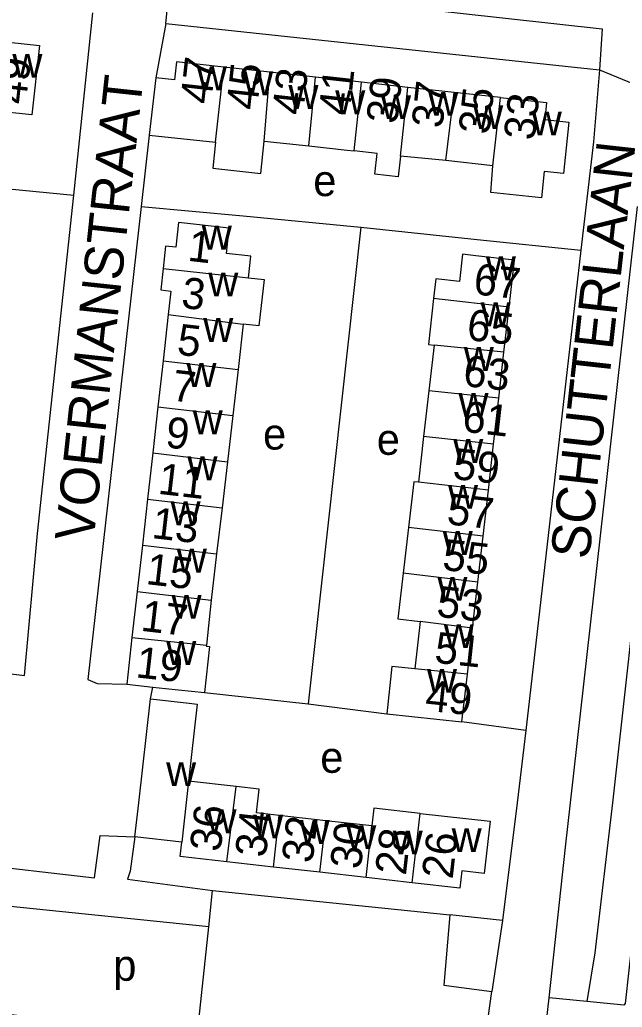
# Model space of a CAD drawing. Extents: x 161936 to 163647, y 386450 to 388633.
# Drawn here: x 162637.9 to 162715.4, y 387223.7 to 387350.8 of the extents above; entities that cross this region are included whole.
import ezdxf

# ---------------------------------------------------------------- set-up
doc = ezdxf.new("R2010")
doc.units = 0
for name, color, linetype in [('BLT_Basislijn', 7, 'Continuous'), ('BLT_Bebouwing', 7, 'Continuous'), ('BLT_Centroide', 7, 'Continuous'), ('BLT_Huisnummer', 7, 'Continuous'), ('BLT_Huisnummer_ tussenligend', 7, 'Continuous'), ('BLT_Onderverdeling_panden', 7, 'Continuous'), ('BLT_Straatnaam', 7, 'Continuous'), ('BLT_Vlakafsluiter', 7, 'Continuous')]:
    doc.layers.add(name, color=color, linetype=linetype)

msp = doc.modelspace()

# ---------------------------------------------------------------- linework, layer by layer
at = {"layer": 'BLT_Basislijn'}
for p, q in [((162656.65, 387350.3), (162657.23, 387355.77)), ((162644.82, 387328.18), (162647.28, 387351.66)), ((162656.65, 387350.3), (162655.35, 387343.29)), ((162656.65, 387350.3), (162712.42, 387344.32)), ((162724.15, 387340.98), (162714.12, 387250)), ((162654.53, 387335.94), (162653.5, 387326.75)), ((162708.71, 387250), (162717.32, 387326.72)), ((162681.73, 387324.06), (162674.96, 387262.75)), ((162710.03, 387321.12), (162702.97, 387259.3)), ((162654.7, 387263.39), (162654.97, 387264.9)), ((162661.63, 387264.19), (162674.96, 387262.75)), ((162674.96, 387262.75), (162685.1, 387261.47)), ((162702.97, 387259.3), (162694.74, 387260.41)), ((162702.97, 387259.3), (162701.83, 387250)), ((162701.83, 387250), (162699.98, 387234.84)), ((162708.08, 387244.31), (162708.71, 387250)), ((162705.96, 387224.92), (162708.08, 387244.31)), ((162662.18, 387234.04), (162662.64, 387238.71)), ((162662.64, 387238.71), (162693.18, 387235.57)), ((162699.98, 387234.84), (162693.18, 387235.57)), ((162660.69, 387219.97), (162662.18, 387234.04)), ((162699.98, 387234.84), (162698.57, 387225.71)), ((162697.71, 387219.57), (162698.57, 387225.71)), ((162705.32, 387219.12), (162705.96, 387224.92)), ((162710.8, 387224.44), (162705.96, 387224.92))]:
    msp.add_line(p, q, dxfattribs=at)
for points in [[(162657.23, 387355.77), (162712.78, 387349.62)], [(162712.78, 387349.62), (162712.42, 387344.32)], [(162712.42, 387344.32), (162711.67, 387335.06), (162710.03, 387321.12)], [(162616.29, 387331.01), (162631.13, 387329.54), (162644.82, 387328.18)], [(162629.16, 387267.52), (162631.11, 387267.3), (162638.46, 387266.37), (162640.15, 387284.64), (162644.82, 387328.18)], [(162653.5, 387326.75), (162646.61, 387265.85), (162647.84, 387265.35), (162651.62, 387265.26)], [(162653.5, 387326.75), (162666.58, 387325.52), (162681.73, 387324.06)], [(162681.73, 387324.06), (162696.69, 387322.5), (162710.03, 387321.12)], [(162714.12, 387250), (162711.86, 387230.69), (162710.8, 387224.44)], [(162623.39, 387248.74), (162629.53, 387248.09), (162629, 387242.28), (162631.09, 387242.25), (162647.49, 387240.34), (162648.2, 387245.8), (162652.68, 387245.62)], [(162652.68, 387245.62), (162652.07, 387241.22), (162651.72, 387240.16), (162662.64, 387238.71)], [(162662.18, 387234.04), (162636.24, 387236.71), (162634.86, 387222.99), (162660.69, 387219.97)], [(162693.18, 387235.57), (162692.4, 387226.54), (162698.57, 387225.71)], [(162716.7, 387232.75), (162715.73, 387224.18), (162715.57, 387223.96), (162710.8, 387224.44)]]:
    msp.add_lwpolyline(points, dxfattribs=at)
at = {"layer": 'BLT_Bebouwing'}
for p, q in [((162670.02, 387344.03), (162664.11, 387344.68)), ((162655.35, 387343.29), (162654.53, 387335.94)), ((162675.89, 387343.39), (162670.02, 387344.03)), ((162681.84, 387342.73), (162675.89, 387343.39)), ((162687.79, 387342.07), (162681.84, 387342.73)), ((162693.74, 387341.42), (162687.79, 387342.07)), ((162699.7, 387340.76), (162693.74, 387341.42)), ((162654.53, 387335.94), (162663.04, 387335)), ((162692.68, 387332.64), (162686.84, 387333.23)), ((162656.95, 387312.84), (162656.29, 387306.9)), ((162700.15, 387308.01), (162700.81, 387313.78)), ((162699.48, 387302.08), (162700.15, 387308.01)), ((162656.29, 387306.9), (162655.62, 387300.96)), ((162665.97, 387305.78), (162665.29, 387299.84)), ((162690.5, 387303.03), (162689.82, 387297.14)), ((162698.81, 387296.16), (162699.48, 387302.08)), ((162655.62, 387300.96), (162654.96, 387295.02)), ((162689.82, 387297.14), (162689.15, 387291.25)), ((162698.14, 387290.24), (162698.81, 387296.16)), ((162654.96, 387295.02), (162654.29, 387289.08)), ((162664.58, 387293.9), (162663.88, 387287.97)), ((162697.46, 387284.32), (162698.14, 387290.24)), ((162654.29, 387289.08), (162653.63, 387283.14)), ((162663.88, 387287.97), (162663.18, 387282.03)), ((162687.86, 387285.43), (162687.18, 387279.55)), ((162696.79, 387278.39), (162697.46, 387284.32)), ((162653.63, 387283.14), (162652.96, 387277.2)), ((162663.18, 387282.03), (162662.48, 387276.09)), ((162696.12, 387272.47), (162696.79, 387278.39)), ((162652.96, 387277.2), (162652.3, 387271.26)), ((162662.48, 387276.09), (162661.87, 387270.29)), ((162689.39, 387273.35), (162688.69, 387267.25)), ((162695.44, 387266.55), (162696.12, 387272.47)), ((162652.3, 387271.26), (162651.62, 387265.26)), ((162694.74, 387260.41), (162695.44, 387266.55)), ((162651.62, 387265.26), (162654.97, 387264.9)), ((162653.18, 387250), (162654.7, 387263.39)), ((162685.1, 387261.47), (162694.74, 387260.41)), ((162665.71, 387252.08), (162659.59, 387252.78)), ((162652.68, 387245.62), (162653.18, 387250)), ((162677.24, 387247.7), (162671.24, 387248.38)), ((162683.17, 387247.03), (162677.24, 387247.7)), ((162658.71, 387244.93), (162652.68, 387245.62)), ((162670.49, 387241.74), (162664.49, 387242.42)), ((162676.48, 387241.06), (162670.49, 387241.74)), ((162682.42, 387240.38), (162676.48, 387241.06)), ((162688.36, 387239.71), (162682.42, 387240.38))]:
    msp.add_line(p, q, dxfattribs=at)
for points in [[(162634.44, 387348.1), (162640.38, 387347.44), (162639.4, 387338.52), (162634.43, 387339.06), (162633.43, 387339.17)], [(162664.11, 387344.68), (162658.03, 387345.36), (162657.78, 387343.03), (162655.35, 387343.29)], [(162699.7, 387340.76), (162705.64, 387340.11), (162705.4, 387337.94), (162708.5, 387337.6), (162707.79, 387330.97), (162705.34, 387331.24), (162704.96, 387327.85), (162698.48, 387328.56), (162698.73, 387331.97)], [(162663.04, 387335), (162662.68, 387331.68), (162668.86, 387331), (162669.32, 387335.16)], [(162669.32, 387335.16), (162675.03, 387334.53)], [(162675.03, 387334.53), (162679.97, 387333.99), (162680.86, 387333.89)], [(162686.84, 387333.23), (162686.55, 387330.57), (162683.55, 387330.91), (162683.84, 387333.56), (162680.86, 387333.89)], [(162698.73, 387331.97), (162692.68, 387332.64)], [(162667.28, 387317.58), (162667.59, 387320.35), (162664.45, 387320.69), (162664.82, 387323.97), (162658.28, 387324.69), (162657.92, 387321.49), (162656.62, 387321.64), (162656.29, 387318.75)], [(162700.81, 387313.78), (162701.5, 387319.84), (162696.53, 387320.41), (162694.82, 387320.6), (162694.42, 387317.09), (162691.37, 387317.43), (162691.09, 387314.89)], [(162656.29, 387318.75), (162655.99, 387316), (162657.29, 387315.86), (162656.95, 387312.84)], [(162667.28, 387317.58), (162669.3, 387317.36), (162668.62, 387311.37), (162666.62, 387311.6)], [(162691.09, 387314.89), (162690.44, 387308.99), (162691.18, 387308.91)], [(162666.62, 387311.6), (162665.97, 387305.78)], [(162691.18, 387308.91), (162690.5, 387303.03)], [(162665.29, 387299.84), (162664.58, 387293.9)], [(162689.15, 387291.25), (162688.54, 387291.32), (162687.86, 387285.43)], [(162687.18, 387279.55), (162686.51, 387273.66), (162689.39, 387273.35)], [(162661.87, 387270.29), (162661.86, 387270.15), (162662.26, 387270.11), (162661.63, 387264.19)], [(162688.69, 387267.25), (162685.74, 387267.56), (162685.1, 387261.47)], [(162654.97, 387264.9), (162656.6, 387264.73), (162661.63, 387264.19)], [(162654.7, 387263.39), (162659.67, 387262.83), (162660.68, 387262.71), (162659.59, 387252.78)], [(162671.24, 387248.38), (162668.32, 387248.72), (162668.66, 387251.74), (162665.71, 387252.08)], [(162689.37, 387248.64), (162683.43, 387249.31), (162683.17, 387247.03)], [(162689.37, 387248.64), (162698.36, 387247.62), (162697.6, 387240.91), (162694.72, 387241.24), (162694.46, 387239.01), (162688.36, 387239.71)], [(162664.49, 387242.42), (162658.5, 387243.1), (162658.71, 387244.93)]]:
    msp.add_lwpolyline(points, dxfattribs=at)
at = {"layer": 'BLT_Onderverdeling_panden'}
for p, q in [((162663.04, 387335), (162664.11, 387344.68)), ((162669.32, 387335.16), (162670.02, 387344.03)), ((162675.03, 387334.53), (162675.89, 387343.39)), ((162680.86, 387333.89), (162681.84, 387342.73)), ((162686.84, 387333.23), (162687.79, 387342.07)), ((162692.68, 387332.64), (162693.74, 387341.42)), ((162698.73, 387331.97), (162699.7, 387340.76)), ((162656.29, 387318.75), (162667.28, 387317.58)), ((162700.81, 387313.78), (162691.09, 387314.89)), ((162656.95, 387312.84), (162666.62, 387311.6)), ((162700.15, 387308.01), (162691.18, 387308.91)), ((162656.29, 387306.9), (162665.97, 387305.78)), ((162699.48, 387302.08), (162690.5, 387303.03)), ((162655.62, 387300.96), (162665.29, 387299.84)), ((162698.81, 387296.16), (162689.82, 387297.14)), ((162654.96, 387295.02), (162664.58, 387293.9)), ((162698.14, 387290.24), (162689.15, 387291.25)), ((162654.29, 387289.08), (162663.88, 387287.97)), ((162697.46, 387284.32), (162687.86, 387285.43)), ((162653.63, 387283.14), (162663.18, 387282.03)), ((162696.79, 387278.39), (162687.18, 387279.55)), ((162652.96, 387277.2), (162662.48, 387276.09)), ((162696.12, 387272.47), (162689.39, 387273.35)), ((162652.3, 387271.26), (162661.87, 387270.29)), ((162695.44, 387266.55), (162688.69, 387267.25)), ((162659.59, 387252.78), (162658.71, 387244.93)), ((162664.49, 387242.42), (162665.71, 387252.08)), ((162670.49, 387241.74), (162671.24, 387248.38)), ((162688.36, 387239.71), (162689.37, 387248.64)), ((162676.48, 387241.06), (162677.24, 387247.7)), ((162682.42, 387240.38), (162683.17, 387247.03))]:
    msp.add_line(p, q, dxfattribs=at)
at = {"layer": 'BLT_Vlakafsluiter'}
msp.add_line((162712.42, 387344.32), (162719.5, 387341.42), dxfattribs=at)

# ---------------------------------------------------------------- texts
at = {"layer": 'BLT_Centroide'}
for s, p in [('w', (162636.91, 387343.3)), ('w', (162660.64, 387341.7)), ('w', (162666.59, 387341.05)), ('w', (162672.42, 387339.3)), ('w', (162678.44, 387338.62)), ('w', (162684.33, 387337.98)), ('w', (162690.41, 387338.42)), ('w', (162696.19, 387336.7)), ('w', (162703.73, 387335.88)), ('e', (162675.62, 387328.08)), ('w', (162661.28, 387321.19)), ('w', (162697.82, 387317.25)), ('w', (162662.11, 387315.16)), ('w', (162697.15, 387311.34)), ('w', (162661.46, 387309.31)), ('w', (162694.98, 387305.59)), ('w', (162659.3, 387303.53)), ('w', (162694.3, 387299.66)), ('w', (162660.11, 387297.44)), ('e', (162669.16, 387295.46)), ('e', (162683.79, 387294.78)), ('w', (162693.62, 387293.75)), ('w', (162659.43, 387291.5)), ('w', (162692.95, 387287.84)), ('w', (162657.26, 387285.72)), ('w', (162692.27, 387281.91)), ('w', (162658.06, 387279.62)), ('w', (162691.59, 387276)), ('w', (162657.38, 387273.69)), ('w', (162692.41, 387269.91)), ('w', (162656.7, 387267.75)), ('w', (162690.24, 387264.16)), ('e', (162676.52, 387253.86)), ('w', (162656.69, 387252.16)), ('w', (162661.88, 387246.08)), ('w', (162667.88, 387245.41)), ('w', (162673.86, 387244.72)), ('w', (162679.86, 387244.05)), ('w', (162693.42, 387243.66)), ('w', (162685.84, 387243.36)), ('p', (162649.89, 387227.1))]:
    msp.add_text(s, height=4, dxfattribs=at).set_placement(p)
at = {"layer": 'BLT_Huisnummer'}
for s, rotation, p in [('49', 83.7098, (162638.64, 387339.79)), ('47', 83.7052, (162662.48, 387339.82)), ('41', 83.7018, (162680.27, 387338.38)), ('37', 83.7071, (162692.22, 387336.72)), ('33', 83.8326, (162704.08, 387335.17)), ('1', 353.4018, (162659.36, 387319.77)), ('67', 353.5104, (162696.12, 387315.47)), ('5', 353.4005, (162657.98, 387307.7)), ('61', 353.5127, (162694.67, 387297.79)), ('9', 353.4041, (162656.49, 387295.76)), ('57', 353.5083, (162692.69, 387285.87)), ('13', 353.4027, (162654.74, 387284.08)), ('53', 353.515, (162691.37, 387273.97)), ('19', 353.5683, (162652.68, 387266.16)), ('49', 353.9952, (162689.91, 387261.88)), ('36', 83.5094, (162663.69, 387243.61)), ('30', 83.5074, (162681.73, 387241.38)), ('26', 83.5189, (162693.54, 387240.1))]:
    msp.add_text(s, height=4, rotation=rotation, dxfattribs=at).set_placement(p)
at = {"layer": 'BLT_Huisnummer_ tussenligend'}
for s, rotation, p in [('45', 83.7018, (162668.39, 387339.06)), ('43', 83.7018, (162674.3, 387338.41)), ('39', 83.7071, (162686.4, 387337.29)), ('35', 83.8326, (162698.26, 387335.92)), ('3', 353.4018, (162658.54, 387313.72)), ('65', 353.5127, (162695.25, 387309.59)), ('63', 353.5127, (162694.78, 387303.67)), ('7', 353.4005, (162657.31, 387301.78)), ('59', 353.5083, (162693.45, 387291.7)), ('11', 353.4041, (162655.54, 387289.78)), ('55', 353.515, (162692.12, 387279.99)), ('15', 353.4027, (162653.99, 387278.16)), ('17', 353.4027, (162653.32, 387272.15)), ('51', 353.9952, (162691.11, 387268.04)), ('34', 83.5074, (162669.51, 387242.88)), ('32', 83.5074, (162675.52, 387242.15)), ('28', 83.5189, (162687.53, 387240.58))]:
    msp.add_text(s, height=4, rotation=rotation, dxfattribs=at).set_placement(p)
at = {"layer": 'BLT_Straatnaam'}
for s, height, rotation, p in [('VOERMANSTRAAT', 4.9999, 83.8531, (162647.34, 387283.48)), ('SCHUTTERLAAN', 5, 83.6325, (162711.11, 387281.24))]:
    msp.add_text(s, height=height, rotation=rotation, dxfattribs=at).set_placement(p)

doc.saveas('drawing.dxf')
